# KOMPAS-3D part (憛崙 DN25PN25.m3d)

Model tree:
1. Объединить компоненты:1  (labels: СЕНС DN25PN25)

Referenced files in D:\Савин\!СЕНСОР\3D для заказчика\!Новый перечень\СЕНС\1. СЕНС\DN25\: СЕНС DN25PN25.a3d
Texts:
  СЕНС DN25PN25
  ООО НПП Сенсор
